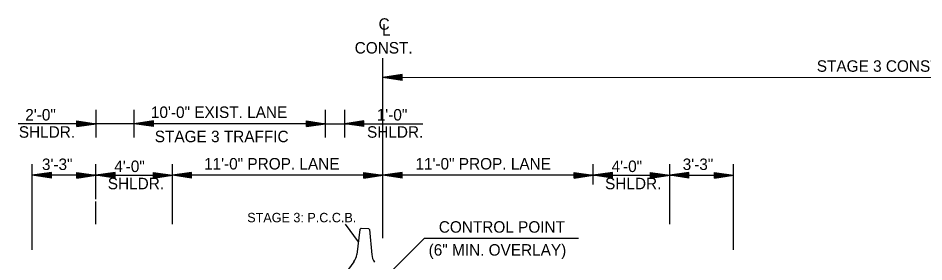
# Model space of a CAD drawing. Extents: x 2829243 to 2838161, y 467639 to 474695.
# Drawn here: x 2830179.9 to 2830653.4, y 468776.7 to 468904.2 of the extents above; entities that cross this region are included whole.
import ezdxf

# ---------------------------------------------------------------- set-up
doc = ezdxf.new("R2010")
doc.units = 0
for name, color, linetype in [('R_Dimension', 7, 'Continuous'), ('R_Draft', 7, 'Continuous'), ('R_MOT', 7, 'Continuous')]:
    doc.layers.add(name, color=color, linetype=linetype)

msp = doc.modelspace()

# ---------------------------------------------------------------- linework, layer by layer
at = {"layer": 'R_Dimension'}
for p, q in [((2830370.56, 468789.01), (2830370.56, 468883.26)), ((2830380.56, 468874.6), (2830370.56, 468873.1)), ((2830932.13, 468872.89), (2830370.56, 468873.1)), ((2830380.56, 468871.6), (2830370.56, 468873.1)), ((2830380.56, 468874.35), (2830372.23, 468873.1)), ((2830380.56, 468871.85), (2830372.23, 468873.1)), ((2830380.56, 468874.09), (2830373.95, 468873.1)), ((2830380.56, 468872.1), (2830373.95, 468873.1)), ((2830380.56, 468873.84), (2830375.62, 468873.1)), ((2830380.56, 468872.35), (2830375.62, 468873.1)), ((2830380.56, 468873.59), (2830377.31, 468873.1)), ((2830380.56, 468872.61), (2830377.31, 468873.1)), ((2830380.56, 468873.33), (2830378.98, 468873.1)), ((2830380.56, 468872.86), (2830378.98, 468873.1)), ((2830380.56, 468871.6), (2830380.56, 468874.6)), ((2830220.62, 468841.67), (2830220.62, 468856.2)), ((2830240.62, 468841.67), (2830240.62, 468856.2)), ((2830340.62, 468841.67), (2830340.62, 468856.2)), ((2830350.62, 468841.67), (2830350.62, 468856.2)), ((2830240.62, 468848.94), (2830179.86, 468848.94)), ((2830210.62, 468850.44), (2830220.62, 468848.94)), ((2830210.62, 468847.44), (2830210.62, 468850.44)), ((2830210.62, 468850.19), (2830218.95, 468848.94)), ((2830210.62, 468849.93), (2830217.23, 468848.94)), ((2830210.62, 468849.68), (2830215.56, 468848.94)), ((2830210.62, 468849.43), (2830213.87, 468848.94)), ((2830210.62, 468849.17), (2830212.2, 468848.94)), ((2830210.62, 468847.44), (2830220.62, 468848.94)), ((2830210.62, 468848.45), (2830213.87, 468848.94)), ((2830210.62, 468847.94), (2830217.23, 468848.94)), ((2830210.62, 468847.69), (2830218.95, 468848.94)), ((2830210.62, 468848.19), (2830215.56, 468848.94)), ((2830210.62, 468848.7), (2830212.2, 468848.94)), ((2830250.62, 468850.44), (2830240.62, 468848.94)), ((2830340.62, 468848.94), (2830240.62, 468848.94)), ((2830250.62, 468847.44), (2830240.62, 468848.94)), ((2830250.62, 468850.19), (2830242.29, 468848.94)), ((2830250.62, 468847.69), (2830242.29, 468848.94)), ((2830250.62, 468849.93), (2830244.01, 468848.94)), ((2830250.62, 468847.94), (2830244.01, 468848.94)), ((2830250.62, 468849.68), (2830245.67, 468848.94)), ((2830250.62, 468848.19), (2830245.67, 468848.94)), ((2830250.62, 468849.43), (2830247.37, 468848.94)), ((2830250.62, 468848.45), (2830247.37, 468848.94)), ((2830250.62, 468849.17), (2830249.04, 468848.94)), ((2830250.62, 468848.7), (2830249.04, 468848.94)), ((2830250.62, 468847.44), (2830250.62, 468850.44)), ((2830330.62, 468850.44), (2830340.62, 468848.94)), ((2830330.62, 468847.44), (2830330.62, 468850.44)), ((2830330.62, 468850.19), (2830338.95, 468848.94)), ((2830330.62, 468849.93), (2830337.23, 468848.94)), ((2830330.62, 468849.68), (2830335.56, 468848.94)), ((2830330.62, 468849.43), (2830333.87, 468848.94)), ((2830330.62, 468849.17), (2830332.2, 468848.94)), ((2830330.62, 468847.44), (2830340.62, 468848.94)), ((2830330.62, 468848.45), (2830333.87, 468848.94)), ((2830330.62, 468847.94), (2830337.23, 468848.94)), ((2830330.62, 468847.69), (2830338.95, 468848.94)), ((2830330.62, 468848.19), (2830335.56, 468848.94)), ((2830330.62, 468848.7), (2830332.2, 468848.94)), ((2830330.62, 468848.94), (2830391.37, 468848.94)), ((2830360.62, 468850.44), (2830350.62, 468848.94)), ((2830360.62, 468850.44), (2830350.62, 468848.94)), ((2830360.62, 468847.44), (2830350.62, 468848.94)), ((2830360.62, 468847.44), (2830350.62, 468848.94)), ((2830360.62, 468850.19), (2830352.29, 468848.94)), ((2830360.62, 468850.19), (2830352.29, 468848.94)), ((2830360.62, 468847.69), (2830352.29, 468848.94)), ((2830360.62, 468847.69), (2830352.29, 468848.94)), ((2830360.62, 468849.93), (2830354.01, 468848.94)), ((2830360.62, 468849.93), (2830354.01, 468848.94)), ((2830360.62, 468847.94), (2830354.01, 468848.94)), ((2830360.62, 468847.94), (2830354.01, 468848.94)), ((2830360.62, 468849.68), (2830355.67, 468848.94)), ((2830360.62, 468849.68), (2830355.67, 468848.94)), ((2830360.62, 468848.19), (2830355.67, 468848.94)), ((2830360.62, 468848.19), (2830355.67, 468848.94)), ((2830360.62, 468849.43), (2830357.37, 468848.94)), ((2830360.62, 468849.43), (2830357.37, 468848.94)), ((2830360.62, 468848.45), (2830357.37, 468848.94)), ((2830360.62, 468848.45), (2830357.37, 468848.94)), ((2830360.62, 468849.17), (2830359.04, 468848.94)), ((2830360.62, 468849.17), (2830359.04, 468848.94)), ((2830360.62, 468848.7), (2830359.04, 468848.94)), ((2830360.62, 468848.7), (2830359.04, 468848.94)), ((2830360.62, 468847.44), (2830360.62, 468850.44)), ((2830360.62, 468847.44), (2830360.62, 468850.44)), ((2830187.23, 468782.9), (2830187.23, 468827.72)), ((2830220.56, 468809.39), (2830220.56, 468827.72)), ((2830260.56, 468796.42), (2830260.56, 468827.72)), ((2830480.56, 468817.22), (2830480.56, 468827.72)), ((2830520.56, 468796.42), (2830520.56, 468827.72)), ((2830553.89, 468782.9), (2830553.89, 468827.72)), ((2830197.23, 468823.48), (2830187.23, 468821.98)), ((2830197.23, 468820.48), (2830187.23, 468821.98)), ((2830220.56, 468821.98), (2830187.79, 468821.98)), ((2830197.23, 468823.23), (2830188.9, 468821.98)), ((2830197.23, 468820.73), (2830188.9, 468821.98)), ((2830197.23, 468822.97), (2830190.62, 468821.98)), ((2830197.23, 468820.98), (2830190.62, 468821.98)), ((2830197.23, 468822.72), (2830192.29, 468821.98)), ((2830197.23, 468821.23), (2830192.29, 468821.98)), ((2830197.23, 468822.47), (2830193.98, 468821.98)), ((2830197.23, 468821.49), (2830193.98, 468821.98)), ((2830197.23, 468822.21), (2830195.65, 468821.98)), ((2830197.23, 468821.74), (2830195.65, 468821.98)), ((2830197.23, 468820.48), (2830197.23, 468823.48)), ((2830210.56, 468823.48), (2830220.56, 468821.98)), ((2830210.56, 468820.48), (2830210.56, 468823.48)), ((2830210.56, 468823.23), (2830218.89, 468821.98)), ((2830210.56, 468822.97), (2830217.17, 468821.98)), ((2830210.56, 468822.72), (2830215.51, 468821.98)), ((2830210.56, 468822.47), (2830213.81, 468821.98)), ((2830210.56, 468822.21), (2830212.14, 468821.98)), ((2830210.56, 468820.48), (2830220.56, 468821.98)), ((2830210.56, 468821.49), (2830213.81, 468821.98)), ((2830210.56, 468820.98), (2830217.17, 468821.98)), ((2830210.56, 468820.73), (2830218.89, 468821.98)), ((2830210.56, 468821.23), (2830215.51, 468821.98)), ((2830210.56, 468821.74), (2830212.14, 468821.98)), ((2830230.56, 468823.48), (2830220.56, 468821.98)), ((2830220.56, 468821.98), (2830260.56, 468821.98)), ((2830230.56, 468820.48), (2830220.56, 468821.98)), ((2830230.56, 468823.23), (2830222.23, 468821.98)), ((2830230.56, 468820.73), (2830222.23, 468821.98)), ((2830230.56, 468822.97), (2830223.95, 468821.98)), ((2830230.56, 468820.98), (2830223.95, 468821.98)), ((2830230.56, 468822.72), (2830225.62, 468821.98)), ((2830230.56, 468821.23), (2830225.62, 468821.98)), ((2830230.56, 468822.47), (2830227.31, 468821.98)), ((2830230.56, 468821.49), (2830227.31, 468821.98)), ((2830230.56, 468822.21), (2830228.98, 468821.98)), ((2830230.56, 468821.74), (2830228.98, 468821.98)), ((2830230.56, 468820.48), (2830230.56, 468823.48)), ((2830250.56, 468823.48), (2830260.56, 468821.98)), ((2830250.56, 468820.48), (2830250.56, 468823.48)), ((2830250.56, 468823.23), (2830258.89, 468821.98)), ((2830250.56, 468822.97), (2830257.17, 468821.98)), ((2830250.56, 468822.72), (2830255.51, 468821.98)), ((2830250.56, 468822.47), (2830253.81, 468821.98)), ((2830250.56, 468822.21), (2830252.14, 468821.98)), ((2830250.56, 468820.48), (2830260.56, 468821.98)), ((2830250.56, 468821.49), (2830253.81, 468821.98)), ((2830250.56, 468820.98), (2830257.17, 468821.98)), ((2830250.56, 468820.73), (2830258.89, 468821.98)), ((2830250.56, 468821.23), (2830255.51, 468821.98)), ((2830250.56, 468821.74), (2830252.14, 468821.98)), ((2830270.56, 468823.48), (2830260.56, 468821.98)), ((2830370.56, 468821.98), (2830260.56, 468821.98)), ((2830270.56, 468820.48), (2830260.56, 468821.98)), ((2830270.56, 468823.23), (2830262.23, 468821.98)), ((2830270.56, 468820.73), (2830262.23, 468821.98)), ((2830270.56, 468822.97), (2830263.95, 468821.98)), ((2830270.56, 468820.98), (2830263.95, 468821.98)), ((2830270.56, 468822.72), (2830265.62, 468821.98)), ((2830270.56, 468821.23), (2830265.62, 468821.98)), ((2830270.56, 468822.47), (2830267.31, 468821.98)), ((2830270.56, 468821.49), (2830267.31, 468821.98)), ((2830270.56, 468822.21), (2830268.98, 468821.98)), ((2830270.56, 468821.74), (2830268.98, 468821.98)), ((2830270.56, 468820.48), (2830270.56, 468823.48)), ((2830360.56, 468823.48), (2830370.56, 468821.98)), ((2830360.56, 468820.48), (2830360.56, 468823.48)), ((2830360.56, 468823.23), (2830368.89, 468821.98)), ((2830360.56, 468822.97), (2830367.17, 468821.98)), ((2830360.56, 468822.72), (2830365.51, 468821.98)), ((2830360.56, 468822.47), (2830363.81, 468821.98)), ((2830360.56, 468822.21), (2830362.14, 468821.98)), ((2830360.56, 468820.48), (2830370.56, 468821.98)), ((2830360.56, 468821.49), (2830363.81, 468821.98)), ((2830360.56, 468820.98), (2830367.17, 468821.98)), ((2830360.56, 468820.73), (2830368.89, 468821.98)), ((2830360.56, 468821.23), (2830365.51, 468821.98)), ((2830360.56, 468821.74), (2830362.14, 468821.98)), ((2830380.56, 468823.48), (2830370.56, 468821.98)), ((2830480.56, 468821.98), (2830370.56, 468821.98)), ((2830380.56, 468820.48), (2830370.56, 468821.98)), ((2830380.56, 468823.23), (2830372.23, 468821.98)), ((2830380.56, 468820.73), (2830372.23, 468821.98)), ((2830380.56, 468822.97), (2830373.95, 468821.98)), ((2830380.56, 468820.98), (2830373.95, 468821.98)), ((2830380.56, 468822.72), (2830375.62, 468821.98)), ((2830380.56, 468821.23), (2830375.62, 468821.98)), ((2830380.56, 468822.47), (2830377.31, 468821.98)), ((2830380.56, 468821.49), (2830377.31, 468821.98)), ((2830380.56, 468822.21), (2830378.98, 468821.98)), ((2830380.56, 468821.74), (2830378.98, 468821.98)), ((2830380.56, 468820.48), (2830380.56, 468823.48)), ((2830470.56, 468823.48), (2830480.56, 468821.98)), ((2830470.56, 468820.48), (2830470.56, 468823.48)), ((2830470.56, 468823.23), (2830478.89, 468821.98)), ((2830470.56, 468822.97), (2830477.17, 468821.98)), ((2830470.56, 468822.72), (2830475.51, 468821.98)), ((2830470.56, 468822.47), (2830473.81, 468821.98)), ((2830470.56, 468822.21), (2830472.14, 468821.98)), ((2830470.56, 468820.48), (2830480.56, 468821.98)), ((2830470.56, 468821.49), (2830473.81, 468821.98)), ((2830470.56, 468820.98), (2830477.17, 468821.98)), ((2830470.56, 468820.73), (2830478.89, 468821.98)), ((2830470.56, 468821.23), (2830475.51, 468821.98)), ((2830470.56, 468821.74), (2830472.14, 468821.98)), ((2830490.56, 468823.48), (2830480.56, 468821.98)), ((2830480.56, 468821.98), (2830520.56, 468821.98)), ((2830490.56, 468820.48), (2830480.56, 468821.98)), ((2830490.56, 468823.23), (2830482.23, 468821.98)), ((2830490.56, 468820.73), (2830482.23, 468821.98)), ((2830490.56, 468822.97), (2830483.95, 468821.98)), ((2830490.56, 468820.98), (2830483.95, 468821.98)), ((2830490.56, 468822.72), (2830485.62, 468821.98)), ((2830490.56, 468821.23), (2830485.62, 468821.98)), ((2830490.56, 468822.47), (2830487.31, 468821.98)), ((2830490.56, 468821.49), (2830487.31, 468821.98)), ((2830490.56, 468822.21), (2830488.98, 468821.98)), ((2830490.56, 468821.74), (2830488.98, 468821.98)), ((2830490.56, 468820.48), (2830490.56, 468823.48)), ((2830510.56, 468823.48), (2830520.56, 468821.98)), ((2830510.56, 468820.48), (2830510.56, 468823.48)), ((2830510.56, 468823.23), (2830518.89, 468821.98)), ((2830510.56, 468822.97), (2830517.17, 468821.98)), ((2830510.56, 468822.72), (2830515.51, 468821.98)), ((2830510.56, 468822.47), (2830513.81, 468821.98)), ((2830510.56, 468822.21), (2830512.14, 468821.98)), ((2830510.56, 468820.48), (2830520.56, 468821.98)), ((2830510.56, 468821.49), (2830513.81, 468821.98)), ((2830510.56, 468820.98), (2830517.17, 468821.98)), ((2830510.56, 468820.73), (2830518.89, 468821.98)), ((2830510.56, 468821.23), (2830515.51, 468821.98)), ((2830510.56, 468821.74), (2830512.14, 468821.98)), ((2830530.56, 468823.48), (2830520.56, 468821.98)), ((2830520.56, 468821.98), (2830553.33, 468821.98)), ((2830530.56, 468820.48), (2830520.56, 468821.98)), ((2830530.56, 468823.23), (2830522.23, 468821.98)), ((2830530.56, 468820.73), (2830522.23, 468821.98)), ((2830530.56, 468822.97), (2830523.95, 468821.98)), ((2830530.56, 468820.98), (2830523.95, 468821.98)), ((2830530.56, 468822.72), (2830525.62, 468821.98)), ((2830530.56, 468821.23), (2830525.62, 468821.98)), ((2830530.56, 468822.47), (2830527.31, 468821.98)), ((2830530.56, 468821.49), (2830527.31, 468821.98)), ((2830530.56, 468822.21), (2830528.98, 468821.98)), ((2830530.56, 468821.74), (2830528.98, 468821.98)), ((2830530.56, 468820.48), (2830530.56, 468823.48)), ((2830543.89, 468823.48), (2830553.89, 468821.98)), ((2830543.89, 468820.48), (2830543.89, 468823.48)), ((2830543.89, 468823.23), (2830552.22, 468821.98)), ((2830543.89, 468822.97), (2830550.5, 468821.98)), ((2830543.89, 468822.72), (2830548.84, 468821.98)), ((2830543.89, 468822.47), (2830547.14, 468821.98)), ((2830543.89, 468822.21), (2830545.47, 468821.98)), ((2830543.89, 468820.48), (2830553.89, 468821.98)), ((2830543.89, 468821.49), (2830547.14, 468821.98)), ((2830543.89, 468820.98), (2830550.5, 468821.98)), ((2830543.89, 468820.73), (2830552.22, 468821.98)), ((2830543.89, 468821.23), (2830548.84, 468821.98)), ((2830543.89, 468821.74), (2830545.47, 468821.98)), ((2830220.56, 468796.42), (2830220.56, 468808.29)), ((2830350.82, 468796.46), (2830357.7, 468787.11)), ((2830370.56, 468767.33), (2830392.31, 468789.08)), ((2830392.31, 468789.08), (2830472.82, 468789.08))]:
    msp.add_line(p, q, dxfattribs=at)
at = {"layer": 'R_MOT'}
for p, q in [((2830358.52, 468793.63), (2830356.89, 468780.59)), ((2830358.52, 468793.63), (2830359.22, 468794.23)), ((2830359.22, 468794.23), (2830362.97, 468794.16)), ((2830362.97, 468794.16), (2830363.65, 468793.52)), ((2830363.65, 468793.52), (2830364.77, 468780.43)), ((2830355.35, 468776.71), (2830350.62, 468770.23))]:
    msp.add_line(p, q, dxfattribs=at)
for centre, start, end in [((2830348.62, 468781.62), 323.8622, 352.8452), ((2830373.07, 468781.14), 184.8632, 213.8462)]:
    msp.add_arc(centre, 8.33, start, end, dxfattribs=at)

# ---------------------------------------------------------------- texts
at = {"layer": 'R_Dimension'}
for s, p in [('C', (2830368.31, 468898.08)), ('L', (2830370.12, 468895.03)), ('CONST.', (2830355.83, 468885.64)), ('STAGE 3 CONSTRUCTION', (2830597.42, 468876.1)), ('2\'-0"', (2830183.61, 468850.61)), ('10\'-0" EXIST. LANE', (2830249.29, 468851.94)), ('1\'-0"', (2830367.36, 468850.61)), ('SHLDR.', (2830180.23, 468841.61)), ('STAGE 3 TRAFFIC', (2830251.3, 468839.26)), ('SHLDR.', (2830362.28, 468841.61)), ('3\'-3"', (2830192.32, 468824.72)), ('4\'-0"', (2830230.12, 468823.65)), ('11\'-0" PROP. LANE', (2830277.07, 468824.98)), ('11\'-0" PROP. LANE', (2830387.59, 468824.98)), ('4\'-0"', (2830490.12, 468823.65)), ('3\'-3"', (2830527.31, 468824.72)), ('SHLDR.', (2830226.74, 468814.65)), ('SHLDR.', (2830486.74, 468814.65)), ('CONTROL POINT', (2830399.8, 468791.93)), ('(6" MIN. OVERLAY)', (2830394.48, 468779.93))]:
    msp.add_text(s, height=6, dxfattribs=at).set_placement(p)
at = {"layer": 'R_Draft'}
msp.add_text('STAGE 3: P.C.C.B.', height=4.9184, dxfattribs=at).set_placement((2830299.65, 468797.38))

doc.saveas('drawing.dxf')
